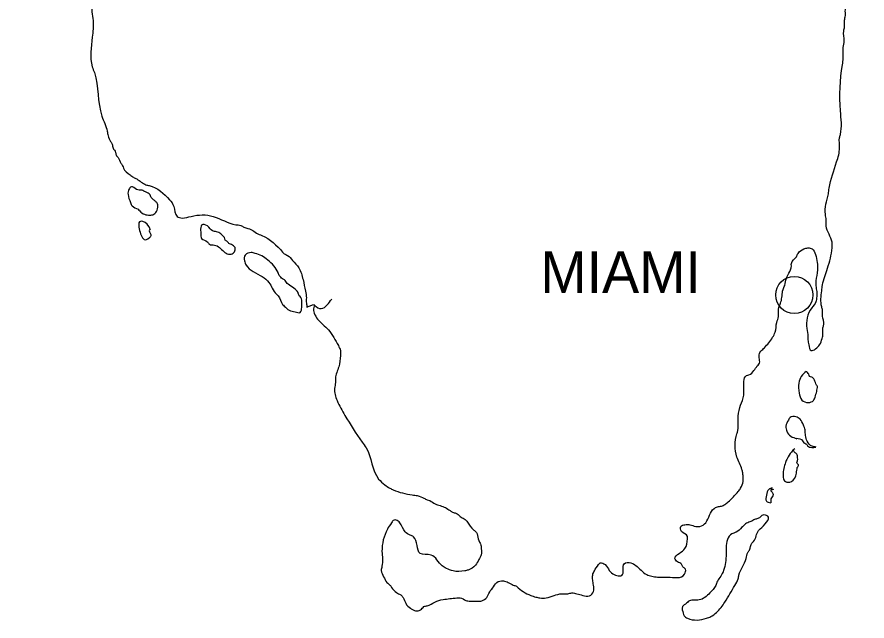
# Model space of a CAD drawing. Extents: x 492225 to 553725, y 1303773 to 1347273.
# Drawn here: x 542228 to 544784, y 1335330 to 1337147 of the extents above; entities that cross this region are included whole.
import ezdxf

# ---------------------------------------------------------------- set-up
doc = ezdxf.new("R2010")
doc.units = 0
doc.layers.add('Level 62', color=7, linetype='Continuous')
doc.layers.add('Level 63', color=7, linetype='Continuous')

msp = doc.modelspace()

# ---------------------------------------------------------------- linework, layer by layer
at = {"layer": 'Level 62'}
msp.add_circle((544565.277, 1336311.2555), 55.9017, dxfattribs=at)
at = {"layer": 'Level 63'}
for points in [[(544594.062, 1336450.0055), (544606.562, 1336452.5055), (544619.062, 1336450.0055), (544629.062, 1336432.5055), (544635.312, 1336386.2555), (544630.312, 1336353.7555), (544630.312, 1336338.7555), (544632.812, 1336321.2555), (544632.812, 1336306.2555), (544630.312, 1336290.0055), (544617.812, 1336272.5055), (544602.812, 1336210.0055), (544606.562, 1336186.2555), (544606.562, 1336176.2555), (544609.062, 1336161.2555), (544616.562, 1336143.7555), (544629.062, 1336148.7555), (544641.562, 1336161.2555), (544649.062, 1336180.0055), (544651.562, 1336195.0055), (544651.562, 1336212.5055), (544654.062, 1336222.5055), (544650.312, 1336247.5055), (544650.312, 1336265.0055), (544647.812, 1336275.0055), (544647.812, 1336323.7555), (544650.312, 1336341.2555), (544665.312, 1336391.2555), (544679.062, 1336452.5055), (544679.062, 1336470.0055), (544661.562, 1336518.7555), (544661.562, 1336536.2555), (544659.062, 1336553.7555), (544660.312, 1336583.7555), (544667.812, 1336615.0055), (544670.312, 1336632.5055), (544692.812, 1336711.2555), (544701.562, 1336753.7555), (544701.562, 1336783.7555), (544704.062, 1336793.7555), (544704.062, 1336865.0055), (544710.312, 1337003.7555), (544712.812, 1337023.7555), (544712.812, 1337055.0055), (544715.312, 1337075.0055), (544714.062, 1337105.0055), (544716.562, 1337117.5055), (544716.562, 1337137.5055), (544719.062, 1337151.2555), (544719.062, 1337168.7555), (544721.562, 1337181.2555), (544721.562, 1337198.7555), (544726.562, 1337228.7555), (544725.312, 1337246.2555), (544727.812, 1337265.0055), (544727.812, 1337292.5055), (544735.312, 1337330.0055), (544735.312, 1337342.5055), (544740.312, 1337363.7555), (544740.312, 1337388.7555), (544742.812, 1337406.2555), (544741.562, 1337458.7555), (544736.562, 1337492.5055), (544736.562, 1337507.5055), (544727.812, 1337567.5055), (544727.812, 1337596.2555), (544725.312, 1337623.7555), (544725.312, 1337683.7555), (544727.812, 1337702.5055), (544726.562, 1337750.0055), (544729.062, 1337760.0055), (544729.062, 1337792.5055), (544731.562, 1337811.2555), (544741.562, 1337826.2555), (544759.062, 1337791.2555), (544761.562, 1337775.0055), (544766.562, 1337757.5055), (544767.812, 1337740.0055), (544772.812, 1337710.0055), (544772.812, 1337692.5055), (544775.312, 1337677.5055), (544776.562, 1337566.2555), (544774.062, 1337547.5055), (544774.062, 1337512.5055), (544771.562, 1337497.5055), (544771.562, 1337482.5055), (544769.062, 1337462.5055), (544769.062, 1337452.5055), (544776.562, 1337455.0055), (544781.562, 1337467.5055), (544784.062, 1337487.5055)], [(542496.562, 1337738.7555), (542509.062, 1337748.7555), (542494.062, 1337728.7555), (542489.062, 1337723.7555), (542439.062, 1337692.5055), (542424.062, 1337685.0055), (542419.062, 1337675.0055), (542409.062, 1337665.0055), (542404.062, 1337657.5055), (542396.562, 1337652.5055), (542394.062, 1337643.7555), (542361.562, 1337606.2555), (542349.062, 1337596.2555), (542339.062, 1337581.2555), (542336.562, 1337565.0055), (542331.562, 1337557.5055), (542330.312, 1337545.0055), (542322.812, 1337527.5055), (542312.812, 1337517.5055), (542295.312, 1337507.5055), (542285.312, 1337500.0055), (542267.812, 1337493.7555), (542252.812, 1337491.2555), (542237.812, 1337483.7555), (542230.312, 1337463.7555), (542227.812, 1337448.7555), (542230.312, 1337433.7555), (542255.312, 1337408.7555), (542265.312, 1337403.7555), (542305.312, 1337391.2555), (542336.562, 1337386.2555), (542399.062, 1337356.2555), (542414.062, 1337343.7555), (542431.562, 1337311.2555), (542434.062, 1337301.2555), (542440.312, 1337288.7555), (542447.812, 1337247.5055), (542447.812, 1337232.5055), (542450.312, 1337220.0055), (542450.312, 1337202.5055), (542452.812, 1337187.5055), (542452.812, 1337162.5055), (542456.562, 1337136.2555), (542456.562, 1337111.2555), (542454.062, 1337086.2555), (542454.062, 1336997.5055), (542460.312, 1336980.0055), (542482.812, 1336848.7555), (542499.062, 1336803.7555), (542501.562, 1336790.0055), (542509.062, 1336772.5055), (542514.062, 1336765.0055), (542516.562, 1336752.5055), (542524.062, 1336740.0055), (542526.562, 1336730.0055), (542531.562, 1336725.0055), (542540.312, 1336707.5055), (542545.312, 1336700.0055), (542547.812, 1336692.5055), (542567.812, 1336672.5055), (542577.812, 1336665.0055), (542587.812, 1336660.0055), (542615.312, 1336642.5055), (542625.312, 1336640.0055), (542686.562, 1336597.5055), (542699.062, 1336577.5055), (542709.062, 1336547.5055), (542724.062, 1336542.5055), (542751.562, 1336547.5055), (542817.812, 1336547.5055), (542885.312, 1336522.5055), (542900.312, 1336520.0055), (542910.312, 1336515.0055), (542932.812, 1336507.5055), (542947.812, 1336497.5055), (542964.062, 1336490.0055), (543026.562, 1336440.0055), (543031.562, 1336435.0055), (543041.562, 1336430.0055), (543056.562, 1336415.0055), (543075.312, 1336392.5055), (543087.812, 1336357.5055), (543095.312, 1336322.5055), (543097.812, 1336302.5055), (543097.812, 1336286.2555), (543100.312, 1336273.7555)], [(542604.062, 1336626.2555), (542586.562, 1336628.7555), (542571.562, 1336636.2555), (542564.062, 1336628.7555), (542561.562, 1336613.7555), (542569.062, 1336588.7555), (542574.062, 1336578.7555), (542591.562, 1336568.7555), (542596.562, 1336563.7555), (542611.562, 1336553.7555), (542626.562, 1336551.2555), (542639.062, 1336553.7555), (542649.062, 1336566.2555), (542651.562, 1336583.7555)], [(542651.562, 1336582.5055), (542647.812, 1336588.7555), (542641.562, 1336595.0055), (542635.312, 1336600.0055), (542630.312, 1336606.2555), (542627.812, 1336612.5055), (542614.062, 1336621.2555), (542604.062, 1336626.2555)], [(542627.812, 1336510.0055), (542606.562, 1336532.5055), (542599.062, 1336532.5055), (542597.812, 1336500.0055), (542605.312, 1336482.5055), (542610.312, 1336477.5055), (542625.312, 1336482.5055)], [(542851.562, 1336483.7555), (542827.812, 1336501.2555), (542815.312, 1336503.7555), (542800.312, 1336518.7555), (542782.812, 1336521.2555), (542780.312, 1336513.7555), (542780.312, 1336496.2555), (542782.812, 1336481.2555), (542800.312, 1336471.2555), (542806.562, 1336463.7555), (542821.562, 1336461.2555), (542836.562, 1336453.7555), (542864.062, 1336433.7555), (542871.562, 1336433.7555), (542881.562, 1336441.2555), (542884.062, 1336453.7555)], [(542627.812, 1336510.0055), (542625.312, 1336503.7555), (542627.812, 1336497.5055), (542630.312, 1336488.7555), (542625.312, 1336482.5055)], [(542884.062, 1336453.7555), (542879.062, 1336458.7555), (542872.812, 1336462.5055), (542866.562, 1336465.0055), (542860.312, 1336471.2555), (542854.062, 1336476.2555), (542851.562, 1336483.7555)], [(543012.812, 1336378.7555), (543000.312, 1336398.7555), (542981.562, 1336416.2555), (542964.062, 1336428.7555), (542944.062, 1336436.2555), (542931.562, 1336438.7555), (542914.062, 1336431.2555), (542911.562, 1336413.7555), (542916.562, 1336401.2555), (542937.812, 1336381.2555), (542965.312, 1336366.2555), (542985.312, 1336348.7555), (542995.312, 1336331.2555), (543007.812, 1336313.7555), (543012.812, 1336308.7555), (543026.562, 1336282.5055), (543031.562, 1336277.5055), (543046.562, 1336265.0055), (543064.062, 1336260.0055), (543079.062, 1336258.7555), (543084.062, 1336273.7555), (543084.062, 1336286.2555), (543081.562, 1336303.7555), (543076.562, 1336308.7555), (543072.812, 1336318.7555), (543060.312, 1336331.2555), (543042.812, 1336343.7555)], [(543730.312, 1335435.0055), (543750.312, 1335418.7555), (543772.812, 1335407.5055), (543787.812, 1335402.5055), (543800.312, 1335400.0055), (543819.062, 1335400.0055), (543866.562, 1335412.5055), (543884.062, 1335412.5055), (543896.562, 1335415.0055), (543911.562, 1335412.5055), (543929.062, 1335407.5055), (543949.062, 1335406.2555), (543961.562, 1335418.7555), (543961.562, 1335438.7555), (543959.062, 1335453.7555), (543959.062, 1335468.7555), (543964.062, 1335481.2555), (543976.562, 1335500.0055), (543981.562, 1335505.0055), (543996.562, 1335500.0055), (544009.062, 1335482.5055), (544024.062, 1335470.0055), (544031.562, 1335467.5055), (544046.562, 1335467.5055), (544054.062, 1335502.5055), (544074.062, 1335505.0055), (544089.062, 1335497.5055), (544121.562, 1335470.0055), (544136.562, 1335465.0055), (544154.062, 1335462.5055), (544185.312, 1335462.5055), (544235.312, 1335471.2555), (544237.812, 1335486.2555), (544230.312, 1335493.7555), (544226.562, 1335501.2555), (544214.062, 1335508.7555), (544206.562, 1335518.7555), (544219.062, 1335533.7555), (544236.562, 1335548.7555), (544244.062, 1335577.5055), (544244.062, 1335585.0055), (544226.562, 1335600.0055), (544224.062, 1335615.0055), (544236.562, 1335620.0055), (544251.562, 1335620.0055), (544269.062, 1335615.0055), (544281.562, 1335615.0055), (544299.062, 1335626.2555), (544324.062, 1335668.7555), (544334.062, 1335673.7555), (544346.562, 1335676.2555), (544356.562, 1335681.2555), (544366.562, 1335688.7555), (544396.562, 1335720.0055), (544404.062, 1335730.0055), (544411.562, 1335750.0055), (544411.562, 1335765.0055), (544410.312, 1335776.2555), (544407.812, 1335786.2555), (544392.812, 1335823.7555), (544392.812, 1335893.7555), (544395.312, 1335902.5055), (544396.562, 1335937.5055), (544401.562, 1335972.5055), (544411.562, 1336001.2555), (544414.062, 1336018.7555), (544414.062, 1336051.2555), (544421.562, 1336068.7555), (544429.062, 1336071.2555), (544444.062, 1336083.7555), (544454.062, 1336097.5055), (544459.062, 1336102.5055), (544460.312, 1336135.0055), (544470.312, 1336147.5055), (544475.312, 1336152.5055), (544500.312, 1336183.7555), (544507.812, 1336198.7555), (544512.812, 1336228.7555), (544517.812, 1336246.2555), (544517.812, 1336258.7555), (544520.312, 1336277.5055), (544525.312, 1336290.0055), (544531.562, 1336327.5055), (544536.562, 1336340.0055), (544541.562, 1336361.2555), (544549.062, 1336376.2555), (544556.562, 1336398.7555), (544556.562, 1336406.2555), (544571.562, 1336426.2555), (544576.562, 1336436.2555), (544594.062, 1336450.0055)], [(543042.812, 1336343.7555), (543037.812, 1336348.7555), (543034.062, 1336355.0055), (543026.562, 1336360.0055), (543016.562, 1336370.0055), (543011.562, 1336380.0055)], [(543100.312, 1336275.0055), (543122.812, 1336280.0055), (543120.312, 1336273.7555), (543121.562, 1336256.2555), (543131.562, 1336238.7555), (543164.062, 1336206.2555), (543194.062, 1336158.7555), (543200.312, 1336143.7555), (543200.312, 1336128.7555), (543195.312, 1336095.0055), (543185.312, 1336060.0055), (543185.312, 1336047.5055), (543182.812, 1336030.0055), (543190.312, 1335993.7555), (543214.062, 1335948.7555), (543265.312, 1335868.7555), (543277.812, 1335851.2555), (543315.312, 1335757.5055), (543334.062, 1335740.0055), (543349.062, 1335730.0055), (543359.062, 1335725.0055), (543416.562, 1335710.0055), (543431.562, 1335707.5055), (543451.562, 1335700.0055), (543461.562, 1335695.0055), (543469.062, 1335692.5055), (543485.312, 1335682.5055), (543500.312, 1335677.5055), (543530.312, 1335662.5055), (543537.812, 1335657.5055), (543547.812, 1335655.0055), (543560.312, 1335645.0055), (543572.812, 1335637.5055), (543582.812, 1335627.5055), (543600.312, 1335605.0055), (543606.562, 1335600.0055), (543611.562, 1335592.5055), (543616.562, 1335572.5055), (543621.562, 1335562.5055), (543624.062, 1335547.5055), (543624.062, 1335530.0055), (543616.562, 1335515.0055), (543606.562, 1335498.7555), (543584.062, 1335483.7555), (543574.062, 1335481.2555), (543539.062, 1335481.2555), (543519.062, 1335488.7555), (543506.562, 1335496.2555), (543472.812, 1335528.7555), (543440.312, 1335533.7555), (543420.312, 1335583.7555), (543410.312, 1335588.7555), (543395.312, 1335598.7555), (543379.062, 1335626.2555), (543374.062, 1335631.2555), (543361.562, 1335633.7555), (543354.062, 1335626.2555), (543341.562, 1335606.2555), (543325.312, 1335540.0055), (543325.312, 1335495.0055), (543322.812, 1335482.5055), (543330.312, 1335463.7555), (543340.312, 1335446.2555), (543349.062, 1335438.7555), (543354.062, 1335431.2555), (543369.062, 1335416.2555), (543381.562, 1335408.7555), (543389.062, 1335401.2555), (543396.562, 1335383.7555), (543411.562, 1335368.7555), (543419.062, 1335363.7555), (543434.062, 1335361.2555), (543446.562, 1335368.7555), (543451.562, 1335373.7555), (543461.562, 1335376.2555), (543484.062, 1335387.5055), (543509.062, 1335395.0055), (543550.312, 1335400.0055), (543560.312, 1335400.0055), (543577.812, 1335392.5055), (543590.312, 1335390.0055), (543612.812, 1335390.0055), (543625.312, 1335391.2555), (543640.312, 1335401.2555), (543652.812, 1335423.7555), (543657.812, 1335428.7555), (543670.312, 1335446.2555), (543690.312, 1335451.2555), (543705.312, 1335446.2555), (543720.312, 1335438.7555), (543730.312, 1335435.0055)], [(543121.562, 1336280.0055), (543142.812, 1336270.0055), (543160.312, 1336281.2555), (543174.062, 1336298.7555)], [(544601.562, 1336081.2555), (544586.562, 1336066.2555), (544579.062, 1336046.2555), (544580.312, 1336016.2555), (544587.812, 1335995.0055), (544607.812, 1335987.5055), (544622.812, 1335993.7555), (544627.812, 1336003.7555), (544632.812, 1336021.2555), (544635.312, 1336036.2555)], [(544635.312, 1336036.2555), (544630.312, 1336043.7555), (544624.062, 1336058.7555), (544617.812, 1336063.7555), (544611.562, 1336066.2555), (544609.062, 1336072.5055), (544600.312, 1336081.2555)], [(544631.562, 1335853.7555), (544619.062, 1335856.2555), (544604.062, 1335871.2555), (544599.062, 1335888.7555), (544597.812, 1335905.0055), (544592.812, 1335920.0055), (544582.812, 1335937.5055), (544570.312, 1335945.0055), (544552.812, 1335942.5055), (544547.812, 1335935.0055), (544540.312, 1335916.2555), (544542.812, 1335901.2555), (544555.312, 1335886.2555), (544572.812, 1335878.7555)], [(544571.562, 1335880.0055), (544590.312, 1335872.5055), (544594.062, 1335866.2555), (544600.312, 1335863.7555), (544605.312, 1335857.5055), (544617.812, 1335852.5055), (544630.312, 1335853.7555)], [(544566.562, 1335848.7555), (544556.562, 1335838.7555), (544544.062, 1335818.7555), (544539.062, 1335807.5055), (544531.562, 1335770.0055), (544534.062, 1335755.0055), (544539.062, 1335750.0055), (544556.562, 1335750.0055), (544571.562, 1335775.0055), (544574.062, 1335792.5055)], [(544574.062, 1335792.5055), (544577.812, 1335800.0055), (544572.812, 1335806.2555), (544575.312, 1335812.5055), (544575.312, 1335821.2555), (544572.812, 1335832.5055), (544566.562, 1335837.5055), (544562.812, 1335846.2555)], [(544499.062, 1335731.2555), (544489.062, 1335726.2555), (544481.562, 1335708.7555), (544481.562, 1335691.2555), (544495.312, 1335686.2555)], [(544492.812, 1335728.7555), (544501.562, 1335726.2555), (544495.312, 1335723.7555), (544499.062, 1335717.5055), (544501.562, 1335711.2555), (544499.062, 1335703.7555), (544495.312, 1335697.5055), (544495.312, 1335686.2555)], [(544407.812, 1335612.5055), (544390.312, 1335597.5055), (544377.812, 1335592.5055), (544360.312, 1335551.2555), (544360.312, 1335531.2555), (544352.812, 1335482.5055), (544344.062, 1335465.0055), (544334.062, 1335450.0055), (544329.062, 1335437.5055), (544311.562, 1335415.0055), (544279.062, 1335393.7555), (544246.562, 1335388.7555), (544241.562, 1335383.7555), (544229.062, 1335373.7555), (544231.562, 1335353.7555), (544234.062, 1335346.2555), (544244.062, 1335338.7555), (544301.562, 1335338.7555), (544314.062, 1335343.7555), (544331.562, 1335356.2555), (544356.562, 1335387.5055), (544386.562, 1335437.5055), (544396.562, 1335457.5055), (544399.062, 1335468.7555), (544420.312, 1335518.7555), (544425.312, 1335536.2555), (544430.312, 1335543.7555), (544437.812, 1335565.0055), (544442.812, 1335570.0055), (544457.812, 1335602.5055), (544462.812, 1335607.5055), (544485.312, 1335646.2555), (544470.312, 1335648.7555), (544462.812, 1335642.5055)], [(544462.812, 1335642.5055), (544452.812, 1335637.5055), (544444.062, 1335635.0055), (544437.812, 1335631.2555), (544425.312, 1335626.2555), (544419.062, 1335622.5055), (544406.562, 1335611.2555)]]:
    msp.add_spline(points, degree=3, dxfattribs=at)

# ---------------------------------------------------------------- texts
at = {"layer": 'Level 62'}
msp.add_text('MIAMI', height=125.0025, dxfattribs=at).set_placement((543801.562, 1336317.5055))

doc.saveas('drawing.dxf')
